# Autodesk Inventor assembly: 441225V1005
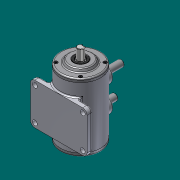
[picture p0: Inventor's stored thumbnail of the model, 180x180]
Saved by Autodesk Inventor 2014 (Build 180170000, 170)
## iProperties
Created: 2014-12
Part Number: 441225V1005
Document SubType Name: Assembly
Designer: user
Author: user
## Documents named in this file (10)
- C:\Users\user\Desktop\441225V1005\441225V1005.iam
- C:\Users\user\Desktop\441225V1005\M4-소켓머리.ipt
- C:\Users\user\Desktop\441225V1005\뒷커버.ipt
- C:\Users\user\Desktop\441225V1005\베어링 6203.ipt
- C:\Users\user\Desktop\441225V1005\본체.ipt
- C:\Users\user\Desktop\441225V1005\부시.ipt
- C:\Users\user\Desktop\441225V1005\슬라이더.ipt
- C:\Users\user\Desktop\441225V1005\앞커버.ipt
- C:\Users\user\Desktop\441225V1005\오일실.ipt
- C:\Users\user\Desktop\441225V1005\축.ipt
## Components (11 placed, 3 different names)
1. 7-베어링 6203:1
2. 8-오일실:1
3. 7-베어링 6203:2
4. 9-M4-소켓머리:1
5. 9-M4-소켓머리:3
6. 9-M4-소켓머리:4
7. 9-M4-소켓머리:5
8. 9-M4-소켓머리:2
9. 9-M4-소켓머리:6
10. 9-M4-소켓머리:7
11. 9-M4-소켓머리:8
